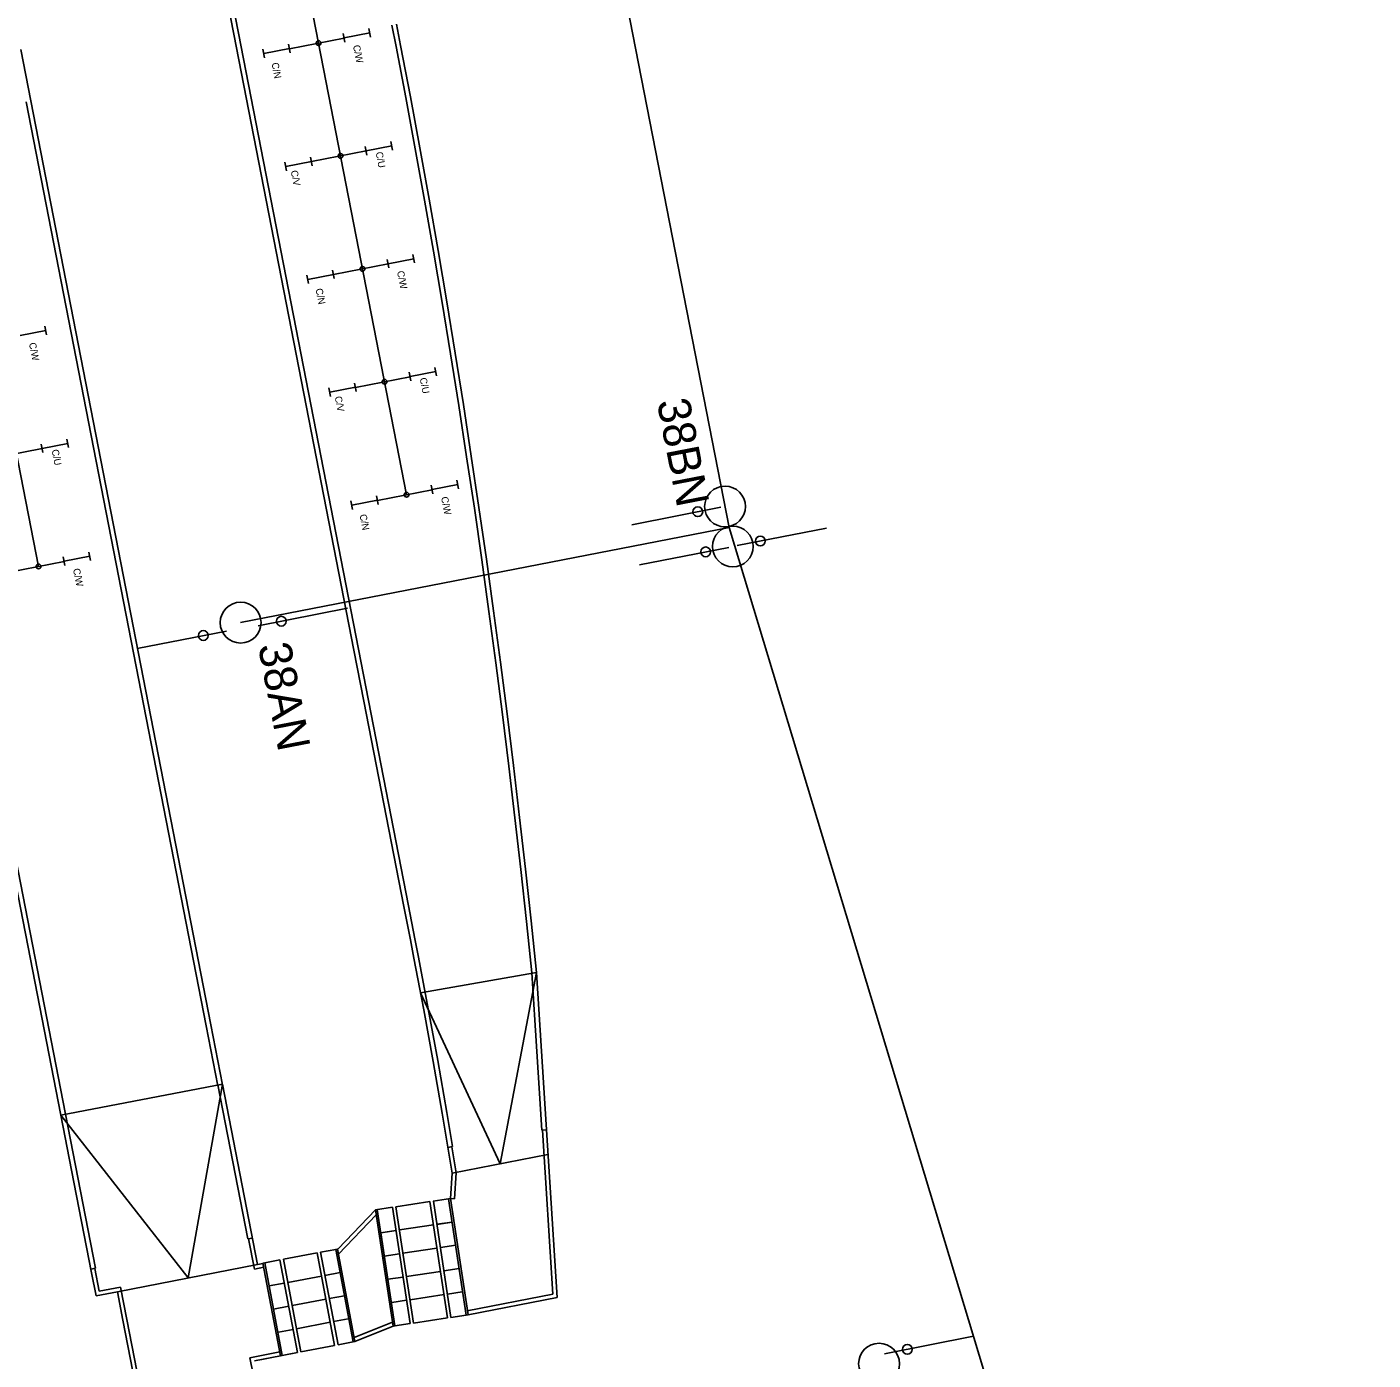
# Model space of a CAD drawing. Extents: x -545258 to -544992, y -1122311 to -1121664.
# Drawn here: x -545154.3 to -545102.8, y -1121948.4 to -1121897.5 of the extents above; entities that cross this region are included whole.
import ezdxf

# ---------------------------------------------------------------- set-up
doc = ezdxf.new("R2010")
doc.units = 0
for name, color, linetype in [('SO 18-01-01_3', 7, 'Continuous'), ('SO 18-01-01_4', 7, 'Continuous'), ('SO18-15-04', 7, 'Continuous'), ('SO18-15-08', 7, 'Continuous'), ('SO18-16-02', 7, 'Continuous'), ('SO18-16-03', 7, 'Continuous'), ('so180605', 7, 'Continuous')]:
    doc.layers.add(name, color=color, linetype=linetype)

msp = doc.modelspace()

# ---------------------------------------------------------------- linework, layer by layer
at = {"layer": 'SO 18-01-01_3'}
for p, q in [((-545127.736, -1121915.824), (-545131.146, -1121916.488)), ((-545146.102, -1121920.234), (-545127.424, -1121916.593)), ((-545127.11, -1121917.29), (-545123.701, -1121916.618)), ((-545127.435, -1121917.356), (-545130.846, -1121918.021)), ((-545145.429, -1121920.354), (-545142.02, -1121919.681)), ((-545146.649, -1121920.555), (-545150.059, -1121921.22)), ((-545121.482, -1121948.204), (-545118.073, -1121947.532))]:
    msp.add_line(p, q, dxfattribs=at)
for centre, radius in [((-545127.577, -1121915.793), 0.78), ((-545128.618, -1121915.995), 0.187), ((-545127.279, -1121917.324), 0.78), ((-545126.229, -1121917.116), 0.187), ((-545128.317, -1121917.528), 0.187), ((-545146.102, -1121920.234), 0.78), ((-545144.548, -1121920.18), 0.187), ((-545147.53, -1121920.727), 0.187), ((-545121.686, -1121948.58), 0.78), ((-545120.601, -1121948.03), 0.187)]:
    msp.add_circle(centre, radius, dxfattribs=at)
at = {"layer": 'SO 18-01-01_4'}
msp.add_lwpolyline([(-545102.793, -1122250.491), (-545106.116, -1122208.618), (-545109.928, -1122137.596), (-545106.412, -1122088.188), (-545106.367, -1122023.596), (-545108.703, -1121978.559), (-545127.424, -1121916.593), (-545139.015, -1121857.213), (-545147.82, -1121812.064), (-545159.299, -1121753.172), (-545170.035, -1121688.35), (-545174.127, -1121676.058)], dxfattribs=at)
at = {"layer": 'SO18-15-04'}
for centre in [(-545143.122, -1121898.068), (-545142.28, -1121902.386), (-545141.438, -1121906.705), (-545140.596, -1121911.024), (-545139.754, -1121915.343), (-545153.83, -1121918.086)]:
    msp.add_circle(centre, 0.09, dxfattribs=at)
at = {"layer": 'SO18-16-02'}
for p, q in [((-545139.223, -1121934.399), (-545134.79, -1121933.612)), ((-545134.587, -1121939.651), (-545134.969, -1121933.623)), ((-545146.798, -1121937.883), (-545152.977, -1121939.071)), ((-545146.975, -1121937.917), (-545145.827, -1121943.807)), ((-545146.798, -1121937.883), (-545145.453, -1121944.782)), ((-545151.652, -1121944.926), (-545152.801, -1121939.037)), ((-545134.587, -1121939.651), (-545134.408, -1121939.639)), ((-545137.997, -1121940.276), (-545138.174, -1121940.306)), ((-545138.01, -1121941.295), (-545134.348, -1121940.581)), ((-545145.65, -1121943.772), (-545145.827, -1121943.807)), ((-545151.652, -1121944.926), (-545151.829, -1121944.96)), ((-545145.453, -1121944.782), (-545150.814, -1121945.827)), ((-545151.629, -1121945.986), (-545150.814, -1121945.827))]:
    msp.add_line(p, q, dxfattribs=at)
for points in [[(-545152.801, -1121939.037), (-545158.129, -1121911.701), (-545158.511, -1121909.738), (-545158.894, -1121907.775), (-545159.277, -1121905.812), (-545159.659, -1121903.849), (-545160.042, -1121901.886), (-545160.425, -1121899.923), (-545160.807, -1121897.96), (-545161.19, -1121895.997), (-545161.572, -1121894.033), (-545161.955, -1121892.07), (-545162.338, -1121890.107), (-545162.72, -1121888.144), (-545163.103, -1121886.181), (-545163.486, -1121884.218), (-545163.868, -1121882.255), (-545164.251, -1121880.292), (-545164.634, -1121878.329), (-545165.016, -1121876.366), (-545165.198, -1121875.433)], [(-545152.977, -1121939.071), (-545158.305, -1121911.735), (-545158.688, -1121909.772), (-545159.071, -1121907.809), (-545159.453, -1121905.846), (-545159.836, -1121903.883), (-545160.219, -1121901.92), (-545160.601, -1121899.957), (-545160.984, -1121897.994), (-545161.367, -1121896.031), (-545161.749, -1121894.068), (-545162.132, -1121892.105), (-545162.514, -1121890.142), (-545162.897, -1121888.179), (-545163.28, -1121886.216), (-545163.662, -1121884.253), (-545164.045, -1121882.29), (-545164.428, -1121880.326), (-545164.81, -1121878.363), (-545165.193, -1121876.4), (-545165.375, -1121875.468)], [(-545140.241, -1121929.133), (-545140.623, -1121927.171), (-545141.006, -1121925.208), (-545141.389, -1121923.245), (-545141.771, -1121921.282), (-545142.154, -1121919.319), (-545142.537, -1121917.356), (-545142.919, -1121915.392), (-545143.302, -1121913.429), (-545143.685, -1121911.466), (-545144.067, -1121909.503), (-545144.45, -1121907.54), (-545144.833, -1121905.577), (-545145.215, -1121903.614), (-545145.598, -1121901.651), (-545145.981, -1121899.688), (-545146.363, -1121897.725), (-545146.746, -1121895.762)], [(-545140.241, -1121929.133), (-545140.623, -1121927.171), (-545141.006, -1121925.208), (-545141.389, -1121923.245), (-545141.771, -1121921.282), (-545142.154, -1121919.319), (-545142.537, -1121917.356), (-545142.919, -1121915.392), (-545143.302, -1121913.429), (-545143.685, -1121911.466), (-545144.067, -1121909.503), (-545144.45, -1121907.54), (-545144.833, -1121905.577), (-545145.215, -1121903.614), (-545145.598, -1121901.651), (-545145.981, -1121899.688), (-545146.363, -1121897.725), (-545146.746, -1121895.762)], [(-545140.064, -1121929.098), (-545140.447, -1121927.136), (-545140.829, -1121925.173), (-545141.212, -1121923.21), (-545141.595, -1121921.247), (-545141.977, -1121919.284), (-545142.36, -1121917.321), (-545142.743, -1121915.358), (-545143.125, -1121913.395), (-545143.508, -1121911.432), (-545143.891, -1121909.469), (-545144.273, -1121907.506), (-545144.656, -1121905.543), (-545145.039, -1121903.58), (-545145.421, -1121901.617), (-545145.804, -1121899.654), (-545146.187, -1121897.691), (-545146.569, -1121895.728)], [(-545140.064, -1121929.098), (-545140.447, -1121927.136), (-545140.829, -1121925.173), (-545141.212, -1121923.21), (-545141.595, -1121921.247), (-545141.977, -1121919.284), (-545142.36, -1121917.321), (-545142.743, -1121915.358), (-545143.125, -1121913.395), (-545143.508, -1121911.432), (-545143.891, -1121909.469), (-545144.273, -1121907.506), (-545144.656, -1121905.543), (-545145.039, -1121903.58), (-545145.421, -1121901.617), (-545145.804, -1121899.654), (-545146.187, -1121897.691), (-545146.569, -1121895.728)], [(-545140.317, -1121897.384), (-545140.159, -1121898.197), (-545139.787, -1121900.154), (-545139.425, -1121902.112), (-545139.072, -1121904.071), (-545138.73, -1121906.032), (-545138.397, -1121907.995), (-545138.074, -1121909.959), (-545137.761, -1121911.925), (-545137.458, -1121913.892), (-545137.164, -1121915.861), (-545136.881, -1121917.832), (-545136.607, -1121919.804), (-545136.343, -1121921.777), (-545136.089, -1121923.751), (-545135.845, -1121925.727), (-545135.611, -1121927.704), (-545135.387, -1121929.682), (-545135.172, -1121931.661), (-545134.969, -1121933.63)], [(-545140.14, -1121897.349), (-545139.982, -1121898.163), (-545139.61, -1121900.121), (-545139.248, -1121902.079), (-545138.895, -1121904.04), (-545138.553, -1121906.001), (-545138.22, -1121907.965), (-545137.897, -1121909.93), (-545137.583, -1121911.897), (-545137.28, -1121913.865), (-545136.986, -1121915.835), (-545136.703, -1121917.807), (-545136.429, -1121919.779), (-545136.165, -1121921.753), (-545135.911, -1121923.729), (-545135.667, -1121925.705), (-545135.432, -1121927.683), (-545135.208, -1121929.662), (-545134.993, -1121931.642), (-545134.79, -1121933.612)], [(-545146.792, -1121937.911), (-545147.24, -1121935.617), (-545147.622, -1121933.654), (-545148.005, -1121931.691), (-545148.388, -1121929.728), (-545148.77, -1121927.765), (-545149.153, -1121925.802), (-545149.536, -1121923.839), (-545149.918, -1121921.876), (-545150.301, -1121919.913), (-545150.684, -1121917.95), (-545151.066, -1121915.987), (-545151.449, -1121914.024), (-545151.831, -1121912.061), (-545152.214, -1121910.098), (-545152.597, -1121908.134), (-545152.979, -1121906.171), (-545153.362, -1121904.208), (-545153.745, -1121902.245), (-545154.127, -1121900.282), (-545154.51, -1121898.319)], [(-545146.969, -1121937.946), (-545147.416, -1121935.652), (-545147.799, -1121933.689), (-545148.182, -1121931.725), (-545148.564, -1121929.762), (-545148.947, -1121927.799), (-545149.33, -1121925.836), (-545149.712, -1121923.873), (-545150.095, -1121921.91), (-545150.478, -1121919.947), (-545150.86, -1121917.984), (-545151.243, -1121916.021), (-545151.626, -1121914.058), (-545152.008, -1121912.095), (-545152.391, -1121910.132), (-545152.773, -1121908.169), (-545153.156, -1121906.206), (-545153.539, -1121904.243), (-545153.921, -1121902.28), (-545154.304, -1121900.317)], [(-545138.008, -1121941.294), (-545138.394, -1121939), (-545138.742, -1121937.019), (-545139.102, -1121935.04), (-545139.475, -1121933.066), (-545139.611, -1121932.363), (-545139.858, -1121931.097), (-545140.241, -1121929.133)], [(-545137.997, -1121940.276), (-545138.217, -1121938.969), (-545138.564, -1121936.987), (-545138.925, -1121935.007), (-545139.298, -1121933.032), (-545139.435, -1121932.329), (-545139.681, -1121931.063), (-545140.064, -1121929.098)], [(-545134.79, -1121933.612), (-545136.179, -1121940.938), (-545139.223, -1121934.399)], [(-545146.798, -1121937.883), (-545148.108, -1121945.3), (-545152.977, -1121939.071)], [(-545152.976, -1121939.074), (-545152.565, -1121941.181), (-545152.183, -1121943.144), (-545151.8, -1121945.107), (-545151.629, -1121945.986)]]:
    msp.add_lwpolyline(points, dxfattribs=at)
at = {"layer": 'SO18-16-03'}
for p, q in [((-545134.002, -1121946.046), (-545134.79, -1121933.612)), ((-545134.16, -1121945.924), (-545134.557, -1121939.649)), ((-545138.078, -1121942.26), (-545138.01, -1121941.295)), ((-545137.928, -1121942.27), (-545137.859, -1121941.279)), ((-545138.078, -1121942.26), (-545138.734, -1121942.359)), ((-545138.731, -1121942.358), (-545138.058, -1121946.808)), ((-545138.147, -1121942.27), (-545137.475, -1121946.719)), ((-545138.078, -1121942.26), (-545137.928, -1121942.27)), ((-545140.946, -1121942.693), (-545142.375, -1121944.183)), ((-545140.917, -1121942.88), (-545142.362, -1121944.387)), ((-545140.946, -1121942.693), (-545140.296, -1121942.595)), ((-545140.876, -1121942.682), (-545140.204, -1121947.132)), ((-545140.293, -1121942.594), (-545139.621, -1121947.044)), ((-545140.165, -1121942.575), (-545138.865, -1121942.378)), ((-545139.489, -1121947.024), (-545140.162, -1121942.574)), ((-545138.19, -1121946.828), (-545138.862, -1121942.378)), ((-545140.03, -1121943.465), (-545138.731, -1121943.268)), ((-545140.027, -1121943.464), (-545138.728, -1121943.268)), ((-545138.016, -1121943.16), (-545138.599, -1121943.249)), ((-545138.013, -1121943.16), (-545138.596, -1121943.248)), ((-545145.797, -1121943.801), (-545145.572, -1121944.958)), ((-545140.745, -1121943.573), (-545140.162, -1121943.485)), ((-545140.742, -1121943.572), (-545140.159, -1121943.484)), ((-545144.469, -1121944.587), (-545143.177, -1121944.343)), ((-545142.509, -1121947.88), (-545143.177, -1121944.343)), ((-545142.467, -1121944.209), (-545143.047, -1121944.318)), ((-545143.047, -1121944.318), (-545142.378, -1121947.856)), ((-545142.467, -1121944.209), (-545141.799, -1121947.746)), ((-545140.607, -1121944.462), (-545140.024, -1121944.374)), ((-545139.893, -1121944.354), (-545138.593, -1121944.158)), ((-545137.878, -1121944.05), (-545138.462, -1121944.138)), ((-545151.51, -1121945.81), (-545151.682, -1121944.932)), ((-545145.218, -1121944.889), (-545145.572, -1121944.958)), ((-545145.246, -1121944.742), (-545145.453, -1121944.782)), ((-545145.179, -1121944.721), (-545144.599, -1121944.612)), ((-545145.179, -1121944.721), (-545144.511, -1121948.259)), ((-545144.599, -1121944.612), (-545143.931, -1121948.149)), ((-545143.8, -1121948.124), (-545144.469, -1121944.587)), ((-545137.744, -1121944.94), (-545138.327, -1121945.028)), ((-545144.302, -1121945.471), (-545143.01, -1121945.227)), ((-545142.3, -1121945.093), (-545142.88, -1121945.203)), ((-545140.473, -1121945.352), (-545139.89, -1121945.264)), ((-545139.758, -1121945.244), (-545138.459, -1121945.048)), ((-545151.51, -1121945.81), (-545150.696, -1121945.651)), ((-545145.012, -1121945.605), (-545144.432, -1121945.496)), ((-545142.133, -1121945.977), (-545142.713, -1121946.087)), ((-545139.624, -1121946.134), (-545138.324, -1121945.938)), ((-545137.629, -1121945.833), (-545138.193, -1121945.918)), ((-545137.434, -1121946.562), (-545134.16, -1121945.924)), ((-545144.845, -1121946.49), (-545144.265, -1121946.38)), ((-545144.134, -1121946.356), (-545142.843, -1121946.112)), ((-545140.319, -1121946.239), (-545139.755, -1121946.154)), ((-545137.406, -1121946.709), (-545134.002, -1121946.046)), ((-545143.967, -1121947.24), (-545142.676, -1121946.996)), ((-545141.985, -1121946.866), (-545142.546, -1121946.971)), ((-545140.296, -1121946.99), (-545141.758, -1121947.583)), ((-545139.489, -1121947.024), (-545138.19, -1121946.827)), ((-545137.475, -1121946.719), (-545138.058, -1121946.808)), ((-545144.658, -1121947.37), (-545144.098, -1121947.265)), ((-545140.273, -1121947.142), (-545141.73, -1121947.733)), ((-545140.204, -1121947.132), (-545139.621, -1121947.044)), ((-545143.8, -1121948.124), (-545142.509, -1121947.88)), ((-545141.799, -1121947.746), (-545142.378, -1121947.856)), ((-545144.609, -1121948.124), (-545145.746, -1121948.351)), ((-545144.58, -1121948.272), (-545145.57, -1121948.469)), ((-545144.128, -1121948.185), (-545145.292, -1121948.412)), ((-545144.511, -1121948.259), (-545143.931, -1121948.149))]:
    msp.add_line(p, q, dxfattribs=at)
for points in [[(-545137.859, -1121941.279), (-545138.027, -1121940.281)], [(-545137.475, -1121946.719), (-545137.406, -1121946.709), (-545138.078, -1121942.26)], [(-545140.946, -1121942.693), (-545140.273, -1121947.142), (-545140.204, -1121947.132), (-545140.742, -1121943.572)], [(-545141.799, -1121947.746), (-545141.73, -1121947.733), (-545142.398, -1121944.196), (-545142.467, -1121944.209), (-545141.799, -1121947.746)], [(-545145.179, -1121944.721), (-545145.248, -1121944.734), (-545144.58, -1121948.272), (-545144.511, -1121948.259), (-545145.179, -1121944.721)], [(-545150.814, -1121945.827), (-545150.603, -1121946.911), (-545150.22, -1121948.875)], [(-545150.696, -1121945.651), (-545150.456, -1121946.883), (-545150.073, -1121948.846)], [(-545145.746, -1121948.351), (-545145.513, -1121949.544)]]:
    msp.add_lwpolyline(points, dxfattribs=at)
at = {"layer": 'so180605'}
for p, q in [((-545141.196, -1121897.515), (-545141.132, -1121897.841)), ((-545142.178, -1121897.704), (-545142.114, -1121898.032)), ((-545142.147, -1121897.87), (-545141.166, -1121897.679)), ((-545145.25, -1121898.302), (-545145.186, -1121898.631)), ((-545145.219, -1121898.469), (-545144.238, -1121898.277)), ((-545144.268, -1121898.114), (-545144.205, -1121898.44)), ((-545141.336, -1121902.022), (-545141.272, -1121902.351)), ((-545141.305, -1121902.189), (-545140.324, -1121901.997)), ((-545140.354, -1121901.834), (-545140.291, -1121902.16)), ((-545144.408, -1121902.621), (-545144.344, -1121902.95)), ((-545144.377, -1121902.787), (-545143.396, -1121902.596)), ((-545143.426, -1121902.433), (-545143.363, -1121902.758)), ((-545140.463, -1121906.507), (-545139.482, -1121906.316)), ((-545139.512, -1121906.153), (-545139.449, -1121906.478)), ((-545142.584, -1121906.751), (-545142.521, -1121907.077)), ((-545140.494, -1121906.341), (-545140.43, -1121906.67)), ((-545143.567, -1121906.94), (-545143.502, -1121907.268)), ((-545143.536, -1121907.106), (-545142.554, -1121906.915)), ((-545153.588, -1121908.896), (-545153.525, -1121909.222)), ((-545154.539, -1121909.251), (-545153.558, -1121909.06)), ((-545139.652, -1121910.66), (-545139.588, -1121910.988)), ((-545139.622, -1121910.826), (-545138.64, -1121910.635)), ((-545138.67, -1121910.471), (-545138.607, -1121910.797)), ((-545142.725, -1121911.259), (-545142.661, -1121911.587)), ((-545142.694, -1121911.425), (-545141.712, -1121911.233)), ((-545141.743, -1121911.07), (-545141.679, -1121911.396)), ((-545153.728, -1121913.404), (-545153.664, -1121913.732)), ((-545153.698, -1121913.57), (-545152.716, -1121913.378)), ((-545152.746, -1121913.215), (-545152.683, -1121913.541)), ((-545138.811, -1121914.979), (-545138.747, -1121915.307)), ((-545138.78, -1121915.145), (-545137.798, -1121914.953)), ((-545137.829, -1121914.79), (-545137.765, -1121915.116)), ((-545141.883, -1121915.577), (-545141.819, -1121915.906)), ((-545141.852, -1121915.743), (-545140.87, -1121915.552)), ((-545140.901, -1121915.389), (-545140.837, -1121915.714)), ((-545151.905, -1121917.534), (-545151.841, -1121917.86)), ((-545152.887, -1121917.722), (-545152.823, -1121918.051)), ((-545152.856, -1121917.889), (-545151.874, -1121917.697))]:
    msp.add_line(p, q, dxfattribs=at)
for points in [[(-545170.396, -1121758.161), (-545139.754, -1121915.343)], [(-545184.472, -1121760.905), (-545153.83, -1121918.086)], [(-545144.235, -1121898.284), (-545142.144, -1121897.877)], [(-545143.393, -1121902.603), (-545141.302, -1121902.196)], [(-545142.551, -1121906.922), (-545140.461, -1121906.515)], [(-545141.709, -1121911.24), (-545139.619, -1121910.833)], [(-545155.785, -1121913.984), (-545153.695, -1121913.577)], [(-545140.868, -1121915.559), (-545138.777, -1121915.152)], [(-545154.944, -1121918.303), (-545152.853, -1121917.896)]]:
    msp.add_lwpolyline(points, dxfattribs=at)

# ---------------------------------------------------------------- texts
at = {"layer": 'SO 18-01-01_3'}
for s, p in [('38BN', (-545130.188, -1121911.778)), ('38AN', (-545145.442, -1121921.118))]:
    msp.add_text(s, height=1.25, rotation=280.9571, dxfattribs=at).set_placement(p)
at = {"layer": 'SO18-15-08'}
for s, p in [('C/W', (-545141.808, -1121898.168)), ('C/N', (-545144.922, -1121898.839)), ('C/U', (-545140.94, -1121902.254)), ('C/V', (-545144.189, -1121902.962)), ('C/W', (-545140.124, -1121906.805)), ('C/N', (-545143.238, -1121907.477)), ('C/W', (-545154.2, -1121909.549)), ('C/U', (-545139.256, -1121910.891)), ('C/V', (-545142.506, -1121911.6)), ('C/U', (-545153.332, -1121913.635)), ('C/W', (-545138.44, -1121915.443)), ('C/N', (-545141.555, -1121916.114)), ('C/W', (-545152.516, -1121918.187))]:
    msp.add_text(s, height=0.2688, rotation=281.121, dxfattribs=at).set_placement(p)

doc.saveas('drawing.dxf')
